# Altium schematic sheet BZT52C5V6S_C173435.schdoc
size 127 x 101 mm
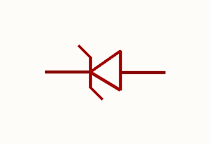
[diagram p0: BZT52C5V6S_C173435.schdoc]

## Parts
D?  bzt52c5v6s_c173435  [SOD-323_L1.8-W1.3-LS2.5-RD]  (value not drawn)

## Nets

Not connected (* = marked no-connect by the designer): D? 1 2

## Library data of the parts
D? = bzt52c5v6s_c173435: 二极管配置:1个独立式;稳压值(标称值):5.6V;稳压值(范围值):5.2V~6V;耗散功率(Pd):200mW;; Manufacturer: MDD(辰达半导体); AddInBom: yes; ModelId: db63db13d9e342eb939127d413d6200b; ModelTransform: 104.3305,51.181,0,0,0,0,0,-0.004,0; Diode Configuration: 1个独立式; Zener Voltage(Nom): 5.6V; Reverse Leakage Current (Ir): 1uA@2.5V; Pd - Power Dissipation: 200mW; Impedance(Zzt): 80Ω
